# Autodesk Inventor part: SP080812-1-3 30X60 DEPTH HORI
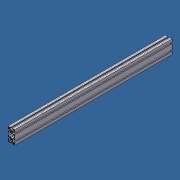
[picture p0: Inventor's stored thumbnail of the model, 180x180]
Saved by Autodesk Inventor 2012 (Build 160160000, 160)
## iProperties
Created: 2012-08
Part Number: SP080812-1-3 30X60 DEPTH HORI
Material: Aluminum-6061
Description: PROFILE 30X60
Document SubType Name: Modeling
Designer: Administrator
Stock Number: 20.0994 PROFILE 30X60
Density: 2.71 g/cm^3
Author: Administrator
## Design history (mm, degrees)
sketch "Sketch1"
  geometry: L1 (-12.5, -19.1)-(-12.5, -21.8); L2 (-15, -19.1)-(-12.5, -19.1); L3 (-15, -30)-(-15, -19.1); L4 (-4.1, -30)-(-15, -30); L5 (-4.1, -27.5)-(-4.1, -30); L6 (-6.8, -27.5)-(-4.1, -27.5); L7 (-6.8, -22.861)-(-6.8, -27.5); L8 (-3.939, -20)-(-6.8, -22.861); L9 (3.939, -20)-(-3.939, -20); L10 (6.8, -22.861)-(3.939, -20); L11 (6.8, -27.5)-(6.8, -22.861); L12 (4.1, -27.5)-(6.8, -27.5); L13 (4.1, -30)-(4.1, -27.5); L14 (15, -30)-(4.1, -30); L15 (15, -19.1)-(15, -30); L16 (12.5, -19.1)-(15, -19.1); L17 (12.5, -21.8)-(12.5, -19.1); L18 (7.861, -21.8)-(12.5, -21.8); L19 (5, -18.939)-(7.861, -21.8); L20 (5, -11.061)-(5, -18.939); L21 (7.861, -8.2)-(5, -11.061); L22 (12.5, -8.2)-(7.861, -8.2); L23 (12.5, -10.9)-(12.5, -8.2); L24 (15, -10.9)-(12.5, -10.9); L25 (15, 10.9)-(15, -10.9); L26 (12.5, 10.9)-(15, 10.9); L27 (12.5, 8.2)-(12.5, 10.9); L28 (7.861, 8.2)-(12.5, 8.2); L29 (5, 11.061)-(7.861, 8.2); L30 (5, 18.939)-(5, 11.061); L31 (7.861, 21.8)-(5, 18.939); L32 (12.5, 21.8)-(7.861, 21.8); L33 (12.5, 19.1)-(12.5, 21.8); L34 (15, 19.1)-(12.5, 19.1); L35 (15, 30)-(15, 19.1); L36 (4.1, 30)-(15, 30); L37 (4.1, 27.5)-(4.1, 30); L38 (6.8, 27.5)-(4.1, 27.5); L39 (6.8, 22.861)-(6.8, 27.5); L40 (3.939, 20)-(6.8, 22.861); L41 (-3.939, 20)-(3.939, 20); L42 (-6.8, 22.861)-(-3.939, 20); L43 (-6.8, 27.5)-(-6.8, 22.861); L44 (-4.1, 27.5)-(-6.8, 27.5); L45 (-4.1, 30)-(-4.1, 27.5); L46 (-15, 30)-(-4.1, 30); L47 (-15, 19.1)-(-15, 30); L48 (-12.5, 19.1)-(-15, 19.1); L49 (-12.5, 21.8)-(-12.5, 19.1); L50 (-7.861, 21.8)-(-12.5, 21.8); L51 (-5, 18.939)-(-7.861, 21.8); L52 (-5, 11.061)-(-5, 18.939); L53 (-7.861, 8.2)-(-5, 11.061); L54 (-12.5, 8.2)-(-7.861, 8.2); L55 (-12.5, 10.9)-(-12.5, 8.2); L56 (-15, 10.9)-(-12.5, 10.9); L57 (-15, -10.9)-(-15, 10.9); L58 (-12.5, -10.9)-(-15, -10.9); L59 (-12.5, -8.2)-(-12.5, -10.9); L60 (-7.861, -8.2)-(-12.5, -8.2); L61 (-5, -11.061)-(-7.861, -8.2); L62 (-5, -18.939)-(-5, -11.061); L63 (-7.861, -21.8)-(-5, -18.939); L64 (-12.5, -21.8)-(-7.861, -21.8)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; A1 r 0.5 centre (13.5, -23.3) between (14, -23.3) and (13.5, -22.8); A2 r 1.5 centre (12.5, -27.5) between (12.5, -29) and (14, -27.5); A3 r 0.5 centre (8.3, -28.5) between (7.8, -28.5) and (8.3, -29); A4 r 1.5 centre (9.3, -24.3) between (9.3, -22.8) and (7.8, -24.3); A5 r 0.5 centre (-8.3, -28.5) between (-8.3, -29) and (-7.8, -28.5); A6 r 1.5 centre (-12.5, -27.5) between (-14, -27.5) and (-12.5, -29); A7 r 0.5 centre (-13.5, -23.3) between (-13.5, -22.8) and (-14, -23.3); A8 r 1.5 centre (-9.3, -24.3) between (-7.8, -24.3) and (-9.3, -22.8); A9 r 0.3 centre (-1.793, -11.369) between (-2.005, -11.581) and (-1.66, -11.638); A10 r 3.75 centre (0, -15) between (1.66, -11.638) and (-1.66, -11.638); A11 r 0.3 centre (1.793, -11.369) between (1.66, -11.638) and (2.005, -11.581); A12 r 0.5 centre (3, -12) between (3.5, -12) and (3, -11.5); A13 r 0.3 centre (3.631, -13.207) between (3.419, -12.995) and (3.362, -13.34); A14 r 3.75 centre (0, -15) between (3.362, -16.66) and (3.362, -13.34); A15 r 0.3 centre (3.631, -16.793) between (3.362, -16.66) and (3.419, -17.005); A16 r 0.5 centre (3, -18) between (3, -18.5) and (3.5, -18); A17 r 0.3 centre (1.793, -18.631) between (2.005, -18.419) and (1.66, -18.362); A18 r 3.75 centre (0, -15) between (-1.66, -18.362) and (1.66, -18.362); A19 r 0.3 centre (-1.793, -18.631) between (-1.66, -18.362) and (-2.005, -18.419); A20 r 0.5 centre (-3, -18) between (-3.5, -18) and (-3, -18.5); A21 r 0.3 centre (-3.631, -16.793) between (-3.419, -17.005) and (-3.362, -16.66); A22 r 3.75 centre (0, -15) between (-3.362, -13.34) and (-3.362, -16.66); A23 r 0.3 centre (-3.631, -13.207) between (-3.362, -13.34) and (-3.419, -12.995); A24 r 0.5 centre (-3, -12) between (-3, -11.5) and (-3.5, -12); A25 r 0.5 centre (13.5, 6.7) between (14, 6.7) and (13.5, 7.2); A26 r 0.5 centre (13.5, -6.7) between (13.5, -7.2) and (14, -6.7); A27 r 1 centre (7.154, -8.2) between (7.154, -7.2) and (6.446, -7.493); A28 r 1 centre (3.525, -9) between (3.525, -10) and (4.232, -9.707); A29 r 1 centre (-3.525, -9) between (-4.232, -9.707) and (-3.525, -10); A30 r 1 centre (-7.154, -8.2) between (-6.446, -7.493) and (-7.154, -7.2); A31 r 0.5 centre (-13.5, -6.7) between (-14, -6.7) and (-13.5, -7.2); A32 r 0.5 centre (-13.5, 6.7) between (-13.5, 7.2) and (-14, 6.7); A33 r 1 centre (-7.154, 8.2) between (-7.154, 7.2) and (-6.446, 7.493); A34 r 1 centre (-3.525, 9) between (-3.525, 10) and (-4.232, 9.707); A35 r 1 centre (3.525, 9) between (4.232, 9.707) and (3.525, 10); A36 r 1 centre (7.154, 8.2) between (6.446, 7.493) and (7.154, 7.2); A37 r 0.3 centre (3.631, 16.793) between (3.419, 17.005) and (3.362, 16.66); A38 r 3.75 centre (0, 15) between (3.362, 13.34) and (3.362, 16.66); A39 r 0.3 centre (3.631, 13.207) between (3.362, 13.34) and (3.419, 12.995); A40 r 0.5 centre (3, 12) between (3, 11.5) and (3.5, 12); A41 r 0.3 centre (1.793, 11.369) between (2.005, 11.581) and (1.66, 11.638); A42 r 3.75 centre (0, 15) between (-1.66, 11.638) and (1.66, 11.638); A43 r 0.3 centre (-1.793, 11.369) between (-1.66, 11.638) and (-2.005, 11.581); A44 r 0.5 centre (-3, 12) between (-3.5, 12) and (-3, 11.5); A45 r 0.3 centre (-3.631, 13.207) between (-3.419, 12.995) and (-3.362, 13.34); A46 r 3.75 centre (0, 15) between (-3.362, 16.66) and (-3.362, 13.34); A47 r 0.3 centre (-3.631, 16.793) between (-3.362, 16.66) and (-3.419, 17.005); A48 r 0.5 centre (-3, 18) between (-3, 18.5) and (-3.5, 18); A49 r 0.3 centre (-1.793, 18.631) between (-2.005, 18.419) and (-1.66, 18.362); A50 r 3.75 centre (0, 15) between (1.66, 18.362) and (-1.66, 18.362); A51 r 0.3 centre (1.793, 18.631) between (1.66, 18.362) and (2.005, 18.419); A52 r 0.5 centre (3, 18) between (3.5, 18) and (3, 18.5); A53 r 0.5 centre (-8.3, 28.5) between (-7.8, 28.5) and (-8.3, 29); A54 r 1.5 centre (-9.3, 24.3) between (-9.3, 22.8) and (-7.8, 24.3); A55 r 0.5 centre (-13.5, 23.3) between (-14, 23.3) and (-13.5, 22.8); A56 r 1.5 centre (-12.5, 27.5) between (-12.5, 29) and (-14, 27.5); A57 r 0.5 centre (13.5, 23.3) between (13.5, 22.8) and (14, 23.3); A58 r 1.5 centre (9.3, 24.3) between (7.8, 24.3) and (9.3, 22.8); A59 r 0.5 centre (8.3, 28.5) between (8.3, 29) and (7.8, 28.5); A60 r 1.5 centre (12.5, 27.5) between (14, 27.5) and (12.5, 29); 1 further point
  constraints: 248 end point, 120 point on circle, 60 centre point
extrude "Extrusion1" new body sketch "Sketch1" stored distance "d3" = 702; taper "d4" = 0 deg
body "Solid1"
